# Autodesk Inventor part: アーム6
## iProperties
Created: 2008-02
Part Number: アーム6
Document SubType Name: Modeling
Designer: y-shimazaki
Density: 1 g/cm^3
Author: y-shimazaki
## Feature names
1. 押し出し1 [Extrusion]
2. 押し出し2 [Extrusion]
